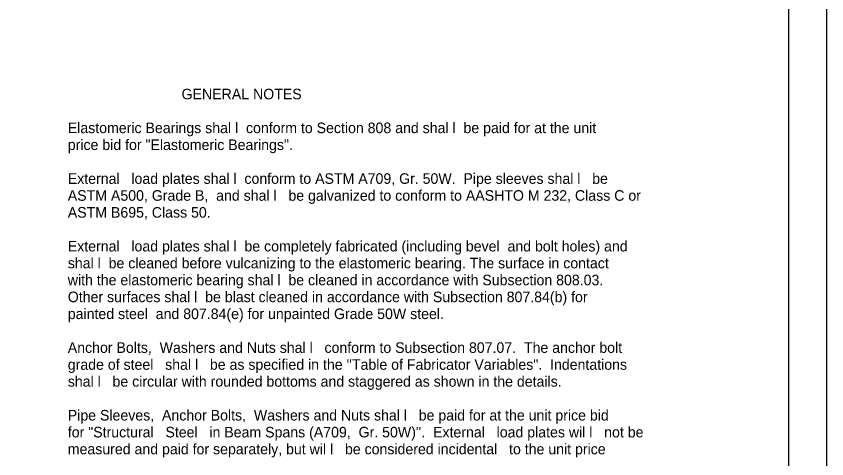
# Model space of a CAD drawing. Extents: x 32334 to 32601, y -901 to -733.
# Drawn here: x 32524.1 to 32600.9, y -859.7 to -817.9 of the extents above; entities that cross this region are included whole.
import ezdxf

# ---------------------------------------------------------------- set-up
doc = ezdxf.new("R2010")
doc.units = 0
for name, color, linetype in [('1', 7, 'Continuous'), ('Level 1', 7, 'Continuous'), ('Level 63', 7, 'Continuous')]:
    doc.layers.add(name, color=color, linetype=linetype)

msp = doc.modelspace()

# ---------------------------------------------------------------- linework, layer by layer
at = {"layer": 'Level 1'}
msp.add_line((32597.265, -898.996), (32597.265, -734.628), dxfattribs=at)
at = {"layer": 'Level 63'}
msp.add_lwpolyline([(32334.224, -900.592), (32600.865, -900.592), (32600.865, -733.016), (32334.224, -733.016)], close=True, dxfattribs=at)

# ---------------------------------------------------------------- texts
at = {"layer": '1'}
for s, p in [('                             GENERAL NOTES', (32529.01, -825.724)), ('Elastomeric Bearings shal l  conform to Section 808 and shal l  be paid for at the unit ', (32529.01, -828.924)), ('price bid for "Elastomeric Bearings".', (32529.01, -830.524)), ('External   load plates shal l  conform to ASTM A709, Gr. 50W.  Pipe sleeves shal l   be', (32529.01, -833.724)), ('ASTM A500, Grade B,  and shal l   be galvanized to conform to AASHTO M 232, Class C or ', (32529.01, -835.324)), ('ASTM B695, Class 50.', (32529.01, -836.924)), ('External   load plates shal l  be completely fabricated (including bevel  and bolt holes) and', (32529.01, -840.124)), ('shal l  be cleaned before vulcanizing to the elastomeric bearing. The surface in contact', (32529.01, -841.724)), ('with the elastomeric bearing shal l  be cleaned in accordance with Subsection 808.03.  ', (32529.01, -843.324)), ('Other surfaces shal l  be blast cleaned in accordance with Subsection 807.84(b) for ', (32529.01, -844.924)), ('painted steel  and 807.84(e) for unpainted Grade 50W steel. ', (32529.01, -846.524)), ('Anchor Bolts,  Washers and Nuts shal l   conform to Subsection 807.07.  The anchor bolt ', (32529.01, -849.724)), ('grade of steel   shal l   be as specified in the \'\'Table of Fabricator Variables".  Indentations ', (32529.01, -851.324)), ('shal l   be circular with rounded bottoms and staggered as shown in the details.', (32529.01, -852.924)), ('Pipe Sleeves,  Anchor Bolts,  Washers and Nuts shal l   be paid for at the unit price bid ', (32529.01, -856.125)), ('for "Structural   Steel   in Beam Spans (A709,  Gr. 50W)\'\'.  External   load plates wil l   not be ', (32529.01, -857.725)), ('measured and paid for separately, but wil l   be considered incidental   to the unit price', (32529.01, -859.325))]:
    msp.add_text(s, height=1, dxfattribs=at).set_placement(p)

doc.saveas('drawing.dxf')
